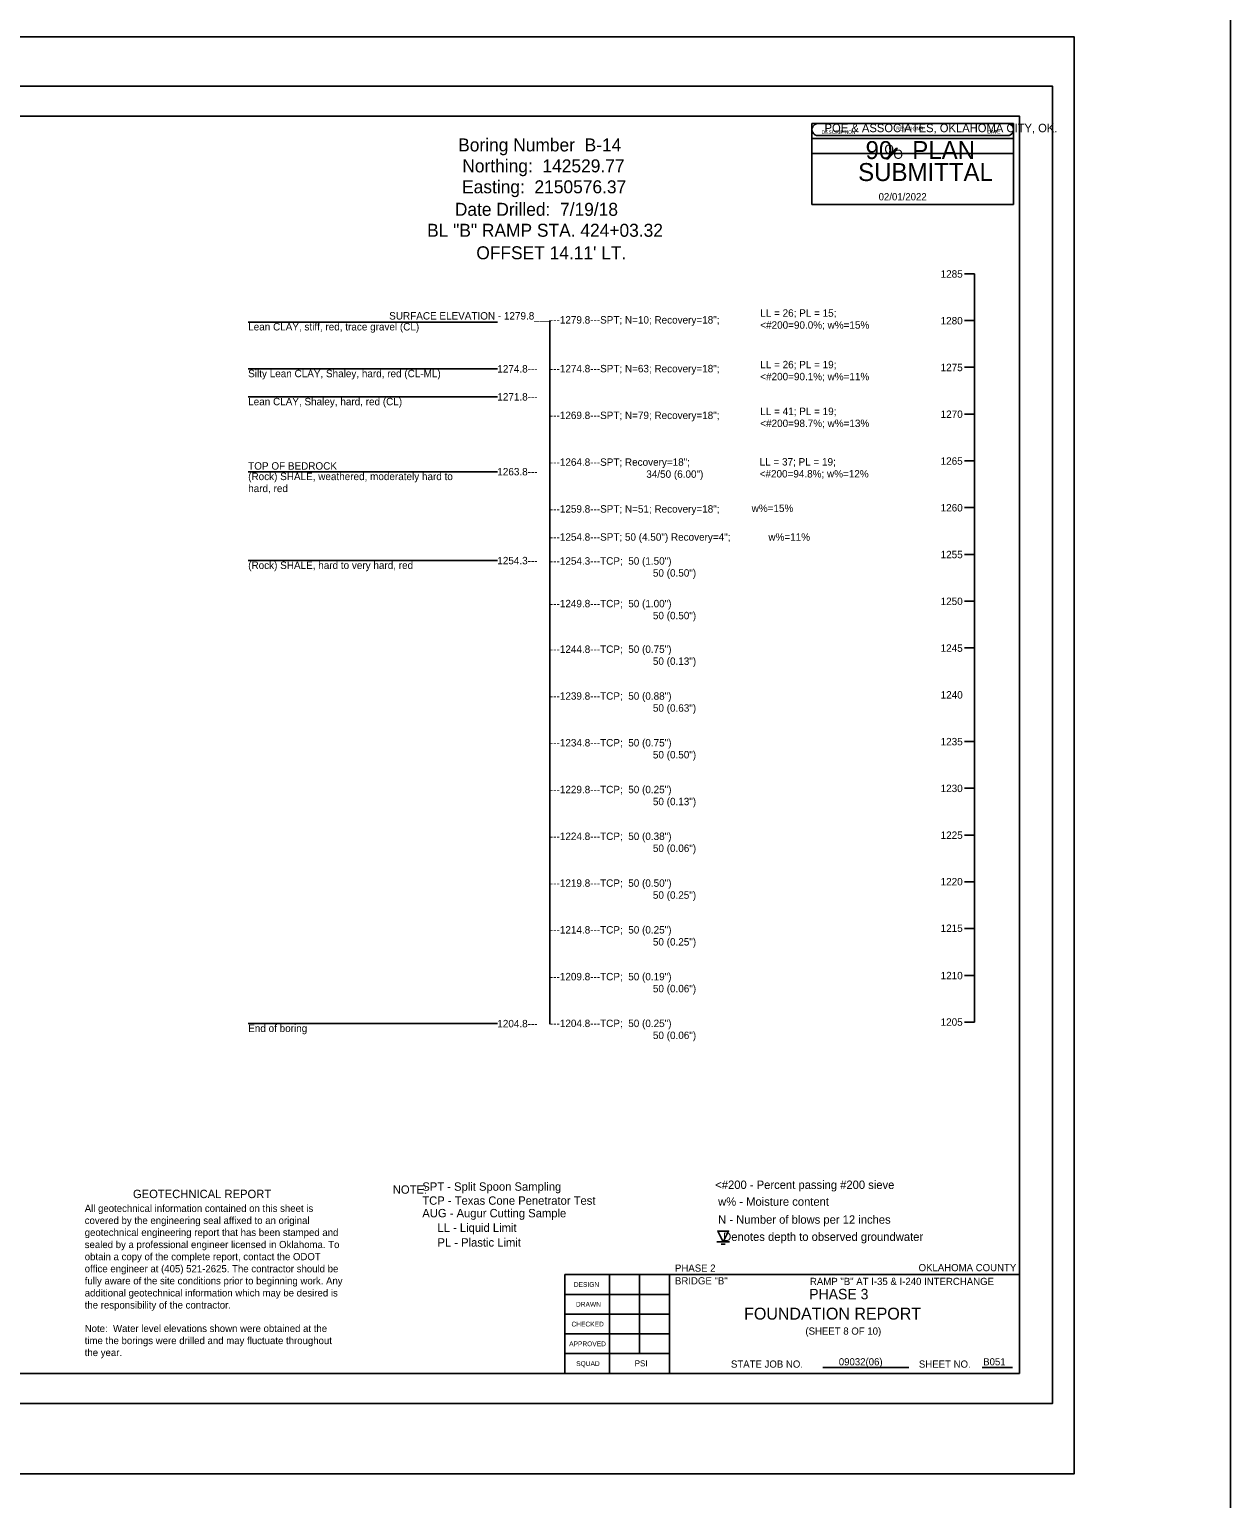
# Model space of a CAD drawing. Extents: x 2150162 to 2150245, y 143729 to 143865.
# Drawn here: x 2150225.17 to 2150245.24, y 143786.22 to 143810.76 of the extents above; entities that cross this region are included whole.
import ezdxf

# ---------------------------------------------------------------- set-up
doc = ezdxf.new("R2010")
doc.units = 0
for name, color, linetype in [('Default', 7, 'Continuous'), ('S', 7, 'Continuous'), ('SHT_Plot_Shape_Full', 7, 'Continuous'), ('SHT_Plot_Shape_Half', 7, 'Continuous'), ('SHT_Sheet_Border', 7, 'Continuous'), ('SHT_Stamp_90_Submit', 7, 'Continuous'), ('SHT_Stamp_Rev_Block', 7, 'Continuous'), ('SHT_Standard_Sheet_Lines', 7, 'Continuous'), ('SHT_Standard_Sheet_Txt', 7, 'Continuous'), ('T', 7, 'Continuous'), ('T-Title', 7, 'Continuous'), ('Text', 7, 'Continuous')]:
    doc.layers.add(name, color=color, linetype=linetype)

# ---------------------------------------------------------------- blocks, each defined once
blk = doc.blocks.new('DGRFC_WTLEV1')
at = {"layer": 'Default'}
for points in [[(-0.0127, 0), (0.0127, 0)], [(0, 0), (0.0106, 0.0212), (-0.0106, 0.0212), (0, 0)], [(-0.0042, -0.0042), (0.0042, -0.0042)]]:
    blk.add_lwpolyline(points, dxfattribs=at)

msp = doc.modelspace()

# ---------------------------------------------------------------- linework, layer by layer
at = {"layer": 'Default'}
msp.add_line((2150240.959, 143794.179), (2150240.959, 143806.679), dxfattribs=at)
for points in [[(2150240.959, 143806.68), (2150240.793, 143806.68)], [(2150228.827, 143805.874), (2150232.994, 143805.874)], [(2150233.865, 143805.899), (2150233.865, 143794.148)], [(2150240.959, 143805.899), (2150240.793, 143805.899)], [(2150233.865, 143805.796), (2150233.865, 143796.072)], [(2150228.827, 143805.092), (2150232.994, 143805.092)], [(2150240.959, 143805.118), (2150240.793, 143805.118)], [(2150240.959, 143805.118), (2150240.793, 143805.118)], [(2150228.827, 143804.624), (2150232.994, 143804.624)], [(2150240.959, 143804.337), (2150240.793, 143804.337)], [(2150228.827, 143803.374), (2150232.994, 143803.374)], [(2150240.959, 143803.555), (2150240.793, 143803.555)], [(2150240.959, 143802.774), (2150240.793, 143802.774)], [(2150228.827, 143801.889), (2150232.994, 143801.889)], [(2150240.959, 143801.993), (2150240.793, 143801.993)], [(2150240.959, 143801.212), (2150240.793, 143801.212)], [(2150240.959, 143800.43), (2150240.793, 143800.43)], [(2150240.959, 143798.867), (2150240.793, 143798.867)], [(2150240.959, 143798.085), (2150240.793, 143798.085)], [(2150240.959, 143797.304), (2150240.793, 143797.304)], [(2150240.959, 143796.523), (2150240.793, 143796.523)], [(2150240.959, 143795.742), (2150240.793, 143795.742)], [(2150240.959, 143794.96), (2150240.793, 143794.96)], [(2150228.827, 143794.155), (2150232.994, 143794.155)], [(2150240.959, 143794.179), (2150240.793, 143794.179)]]:
    msp.add_lwpolyline(points, dxfattribs=at)
at = {"layer": 'S'}
msp.add_lwpolyline([(2150203.404, 143865.061), (2150245.24, 143865.061), (2150245.24, 143729.315), (2150203.404, 143729.315)], close=True, dxfattribs=at)
at = {"layer": 'SHT_Plot_Shape_Full'}
msp.add_lwpolyline([(2150206.628, 143810.637), (2150242.628, 143810.637), (2150242.628, 143786.637), (2150206.628, 143786.637)], close=True, dxfattribs=at)
at = {"layer": 'SHT_Plot_Shape_Half'}
msp.add_lwpolyline([(2150208.265, 143809.812), (2150242.265, 143809.812), (2150242.265, 143787.812), (2150208.265, 143787.812)], close=True, dxfattribs=at)
at = {"layer": 'SHT_Sheet_Border'}
for p, q in [((2150234.115, 143788.312), (2150234.115, 143789.962)), ((2150234.115, 143789.962), (2150241.715, 143789.962)), ((2150235.865, 143788.312), (2150235.865, 143789.962))]:
    msp.add_line(p, q, dxfattribs=at)
msp.add_lwpolyline([(2150241.715, 143788.312), (2150210.215, 143788.312), (2150210.215, 143809.312), (2150241.715, 143809.312)], close=True, dxfattribs=at)
at = {"layer": 'SHT_Stamp_90_Submit'}
for p, q in [((2150238.346, 143809.188), (2150241.512, 143809.188)), ((2150238.246, 143808.938), (2150241.612, 143808.938)), ((2150238.246, 143807.838), (2150238.246, 143808.938)), ((2150238.346, 143808.988), (2150241.512, 143808.988)), ((2150239.489, 143808.599), (2150239.645, 143808.772)), ((2150239.507, 143808.599), (2150239.662, 143808.772)), ((2150239.512, 143808.599), (2150239.667, 143808.772)), ((2150239.52, 143808.599), (2150239.675, 143808.772)), ((2150239.645, 143808.772), (2150239.675, 143808.772)), ((2150241.612, 143807.838), (2150241.612, 143808.938)), ((2150239.489, 143808.599), (2150239.52, 143808.599)), ((2150238.246, 143807.838), (2150241.612, 143807.838))]:
    msp.add_line(p, q, dxfattribs=at)
for centre, start, end in [((2150238.346, 143809.088), 89.9952, 270), ((2150241.512, 143809.088), 270, 90.0048)]:
    msp.add_arc(centre, 0.1, start, end, dxfattribs=at)
at = {"layer": 'SHT_Stamp_Rev_Block'}
for p, q in [((2150238.246, 143809.188), (2150238.246, 143808.688)), ((2150241.612, 143809.188), (2150238.246, 143809.188)), ((2150241.612, 143808.688), (2150241.612, 143809.188)), ((2150241.612, 143808.938), (2150238.246, 143808.938)), ((2150241.612, 143808.688), (2150238.246, 143808.688))]:
    msp.add_line(p, q, dxfattribs=at)
at = {"layer": 'SHT_Standard_Sheet_Lines'}
for p, q in [((2150234.865, 143788.312), (2150234.865, 143789.962)), ((2150235.365, 143788.642), (2150235.365, 143789.962)), ((2150238.426, 143788.408), (2150239.866, 143788.408)), ((2150241.09, 143788.408), (2150241.593, 143788.408))]:
    msp.add_line(p, q, dxfattribs=at)
for points in [[(2150235.865, 143789.632), (2150234.115, 143789.632)], [(2150235.865, 143789.302), (2150234.115, 143789.302)], [(2150235.865, 143788.972), (2150234.115, 143788.972)], [(2150235.865, 143788.642), (2150234.115, 143788.642)]]:
    msp.add_lwpolyline(points, dxfattribs=at)

# ---------------------------------------------------------------- block references
at = {"layer": 'Default', "xscale": 8.503919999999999, "yscale": 8.503919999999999}
msp.add_blockref('DGRFC_WTLEV1', (2150236.762, 143790.508), dxfattribs=at)

# ---------------------------------------------------------------- texts
at = {"layer": 'Default'}
for s, height, p in [('Boring Number  B-14', 0.217, (2150232.335, 143808.724)), ('Northing:  142529.77', 0.217, (2150232.404, 143808.374)), ('Easting:  2150576.37', 0.217, (2150232.4, 143808.024)), ('Date Drilled:  7/19/18', 0.217, (2150232.279, 143807.648)), ('BL "B" RAMP STA. 424+03.32', 0.217, (2150231.816, 143807.298)), ("OFFSET 14.11' LT.", 0.217, (2150232.638, 143806.922)), ('1285', 0.124, (2150240.395, 143806.615)), ('LL = 26; PL = 15;', 0.124, (2150237.382, 143805.962)), ('Lean CLAY, stiff, red, trace gravel (CL)', 0.124, (2150228.827, 143805.733)), ('SURFACE ELEVATION - 1279.8___', 0.124, (2150231.183, 143805.915)), ('---1279.8---SPT; N=10; Recovery=18";', 0.124, (2150233.868, 143805.848)), ('<#200=90.0%; w%=15%', 0.124, (2150237.382, 143805.762)), ('1280', 0.124, (2150240.395, 143805.834)), ('Silty Lean CLAY, Shaley, hard, red (CL-ML)', 0.124, (2150228.827, 143804.952)), ('1274.8---', 0.124, (2150232.989, 143805.03)), ('---1274.8---SPT; N=63; Recovery=18";', 0.124, (2150233.868, 143805.034)), ('LL = 26; PL = 19;', 0.124, (2150237.382, 143805.101)), ('1275', 0.124, (2150240.395, 143805.053)), ('<#200=90.1%; w%=11%', 0.124, (2150237.382, 143804.901)), ('Lean CLAY, Shaley, hard, red (CL)', 0.124, (2150228.827, 143804.483)), ('1271.8---', 0.124, (2150232.989, 143804.562)), ('---1269.8---SPT; N=79; Recovery=18";', 0.124, (2150233.868, 143804.253)), ('LL = 41; PL = 19;', 0.124, (2150237.382, 143804.32)), ('1270', 0.124, (2150240.395, 143804.272)), ('<#200=98.7%; w%=13%', 0.124, (2150237.382, 143804.12)), ('1265', 0.124, (2150240.395, 143803.49)), ('TOP OF BEDROCK', 0.124, (2150228.827, 143803.408)), ('(Rock) SHALE, weathered, moderately hard to', 0.124, (2150228.827, 143803.233)), ('1263.8---', 0.124, (2150232.989, 143803.312)), ('---1264.8---SPT; Recovery=18";', 0.124, (2150233.868, 143803.472)), ('34/50 (6.00")', 0.124, (2150235.478, 143803.272)), ('<#200=94.8%; w%=12%', 0.124, (2150237.372, 143803.277)), ('LL = 37; PL = 19;', 0.124, (2150237.372, 143803.477)), ('hard, red', 0.124, (2150228.827, 143803.033)), ('---1259.8---SPT; N=51; Recovery=18";', 0.124, (2150233.868, 143802.69)), ('w%=15%', 0.124, (2150237.238, 143802.701)), ('1260', 0.124, (2150240.395, 143802.709)), ('---1254.8---SPT; 50 (4.50") Recovery=4";', 0.124, (2150233.868, 143802.221)), ('w%=11%', 0.124, (2150237.518, 143802.222)), ('1254.3---', 0.124, (2150232.989, 143801.827)), ('---1254.3---TCP;  50 (1.50")', 0.124, (2150233.868, 143801.821)), ('1255', 0.124, (2150240.395, 143801.928)), ('(Rock) SHALE, hard to very hard, red', 0.124, (2150228.827, 143801.749)), ('50 (0.50")', 0.124, (2150235.588, 143801.621)), ('---1249.8---TCP;  50 (1.00")', 0.124, (2150233.868, 143801.109)), ('1250', 0.124, (2150240.395, 143801.147)), ('50 (0.50")', 0.124, (2150235.588, 143800.909)), ('---1244.8---TCP;  50 (0.75")', 0.124, (2150233.868, 143800.347)), ('1245', 0.124, (2150240.395, 143800.365)), ('50 (0.13")', 0.124, (2150235.588, 143800.147)), ('---1239.8---TCP;  50 (0.88")', 0.124, (2150233.868, 143799.565)), ('1240', 0.124, (2150240.395, 143799.584)), ('50 (0.63")', 0.124, (2150235.588, 143799.365)), ('---1234.8---TCP;  50 (0.75")', 0.124, (2150233.868, 143798.784)), ('50 (0.50")', 0.124, (2150235.588, 143798.584)), ('1235', 0.124, (2150240.395, 143798.803)), ('---1229.8---TCP;  50 (0.25")', 0.124, (2150233.868, 143798.003)), ('1230', 0.124, (2150240.395, 143798.022)), ('50 (0.13")', 0.124, (2150235.588, 143797.803)), ('---1224.8---TCP;  50 (0.38")', 0.124, (2150233.868, 143797.222)), ('1225', 0.124, (2150240.395, 143797.24)), ('50 (0.06")', 0.124, (2150235.588, 143797.022)), ('---1219.8---TCP;  50 (0.50")', 0.124, (2150233.868, 143796.44)), ('1220', 0.124, (2150240.395, 143796.464)), ('50 (0.25")', 0.124, (2150235.588, 143796.24)), ('---1214.8---TCP;  50 (0.25")', 0.124, (2150233.868, 143795.659)), ('1215', 0.124, (2150240.395, 143795.686)), ('50 (0.25")', 0.124, (2150235.588, 143795.459)), ('1210', 0.124, (2150240.395, 143794.895)), ('---1209.8---TCP;  50 (0.19")', 0.124, (2150233.868, 143794.878)), ('50 (0.06")', 0.124, (2150235.588, 143794.678)), ('End of boring', 0.124, (2150228.827, 143794.014)), ('1204.8---', 0.124, (2150232.989, 143794.093)), ('---1204.8---TCP;  50 (0.25")', 0.124, (2150233.868, 143794.097)), ('1205', 0.124, (2150240.395, 143794.119)), ('50 (0.06")', 0.124, (2150235.588, 143793.897))]:
    msp.add_text(s, height=height, dxfattribs=at).set_placement(p)
at = {"layer": 'Defpoints'}
msp.add_text('PHASE 3', height=0.175, dxfattribs=at).set_placement((2150238.2, 143789.549))
at = {"layer": 'SHT_Stamp_90_Submit'}
for s, height, p in [('POE & ASSOCIATES, OKLAHOMA CITY, OK.', 0.14, (2150238.456, 143809.045)), ('90   PLAN', 0.3, (2150239.141, 143808.596)), ('O', 0.153, (2150239.455, 143808.684)), ('SUBMITTAL', 0.3, (2150239.017, 143808.229)), ('O', 0.153, (2150239.607, 143808.6)), ('02/01/2022', 0.12, (2150239.359, 143807.907))]:
    msp.add_text(s, height=height, dxfattribs=at).set_placement(p)
at = {"layer": 'SHT_Stamp_Rev_Block'}
for s, height, p in [('DESCRIPTION', 0.05999, (2150238.406, 143809.016)), ('REVISIONS', 0.06, (2150239.654, 143809.075)), ('DATE', 0.06, (2150241.175, 143809.02))]:
    msp.add_text(s, height=height, dxfattribs=at).set_placement(p)
at = {"layer": 'SHT_Standard_Sheet_Txt'}
for s, height, p in [('DESIGN', 0.08, (2150234.267, 143789.757)), ('DRAWN', 0.08, (2150234.303, 143789.427)), ('CHECKED', 0.08, (2150234.228, 143789.096)), ('APPROVED', 0.08, (2150234.189, 143788.766)), ('SQUAD', 0.08, (2150234.307, 143788.436)), ('STATE JOB NO.', 0.12, (2150236.892, 143788.408)), ('SHEET NO. ', 0.12, (2150240.032, 143788.408))]:
    msp.add_text(s, height=height, dxfattribs=at).set_placement(p)
at = {"layer": 'T'}
for s, height, p in [('PHASE 2', 0.12, (2150235.957, 143790.011)), ('OKLAHOMA COUNTY', 0.12, (2150240.027, 143790.019)), ('BRIDGE "B"', 0.12, (2150235.957, 143789.799)), ('RAMP "B" AT I-35 & I-240 INTERCHANGE', 0.12, (2150238.212, 143789.789)), ('(SHEET 8 OF 10)', 0.12, (2150238.136, 143788.959)), ('PSI', 0.1, (2150235.284, 143788.43)), ('09032(06)', 0.12, (2150238.694, 143788.446)), ('B051', 0.12, (2150241.106, 143788.446))]:
    msp.add_text(s, height=height, dxfattribs=at).set_placement(p)
at = {"layer": 'T-Title'}
msp.add_text('FOUNDATION REPORT', height=0.2, dxfattribs=at).set_placement((2150237.112, 143789.21))
at = {"layer": 'Text'}
for s, height, p in [('GEOTECHNICAL REPORT', 0.14, (2150226.902, 143791.24)), ('NOTE:', 0.14, (2150231.243, 143791.313)), ('    SPT - Split Spoon Sampling', 0.14, (2150231.528, 143791.363)), (' <#200 - Percent passing #200 sieve', 0.14, (2150236.578, 143791.393)), ('All geotechnical information contained on this sheet is ', 0.12, (2150226.096, 143791.009)), ('    TCP - Texas Cone Penetrator Test', 0.14, (2150231.528, 143791.129)), ('w% - Moisture content', 0.14, (2150236.678, 143791.112)), ('covered by the engineering seal affixed to an original ', 0.12, (2150226.096, 143790.807)), ('    AUG - Augur Cutting Sample', 0.14, (2150231.528, 143790.919)), ('N - Number of blows per 12 inches', 0.14, (2150236.678, 143790.812)), ('geotechnical engineering report that has been stamped and ', 0.12, (2150226.096, 143790.607)), (' LL - Liquid Limit', 0.14, (2150231.937, 143790.676)), ('    Denotes depth to observed groundwater', 0.14, (2150236.554, 143790.525)), ('sealed by a professional engineer licensed in Oklahoma. To ', 0.12, (2150226.096, 143790.405)), (' PL - Plastic Limit', 0.14, (2150231.937, 143790.43)), ('obtain a copy of the complete report, contact the ODOT ', 0.12, (2150226.096, 143790.203)), ('office engineer at (405) 521-2625. The contractor should be ', 0.12, (2150226.096, 143790.001)), ('fully aware of the site conditions prior to beginning work. Any ', 0.12, (2150226.096, 143789.799)), ('additional geotechnical information which may be desired is ', 0.12, (2150226.096, 143789.597)), ('the responsibility of the contractor.', 0.12, (2150226.096, 143789.395)), ('Note:  Water level elevations shown were obtained at the ', 0.12, (2150226.096, 143789.003)), ('time the borings were drilled and may fluctuate throughout ', 0.12, (2150226.096, 143788.801)), ('the year.', 0.12, (2150226.096, 143788.601))]:
    msp.add_text(s, height=height, dxfattribs=at).set_placement(p)

doc.saveas('drawing.dxf')
